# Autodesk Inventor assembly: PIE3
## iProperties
Shininess: 64.0
Length Units: 11269
Angle Units: 11279
Time Units: 11290
Mass Units: 11286
Length Display Precision: 3
Angle Display Precision: 2
Compacted: True
Part Number: PIE3
Document SubType Name: Assembly
Created: 2004-08
Designer: John Blackburn
Manufacturer: Standard
Standards Organization: Custom
Density: 0.0
Volumn: 0.0
Area: 0.0
PropertySet Name: Model Information
Control State: 0
Master: False
Checked Out: False
Author: John Blackburn
